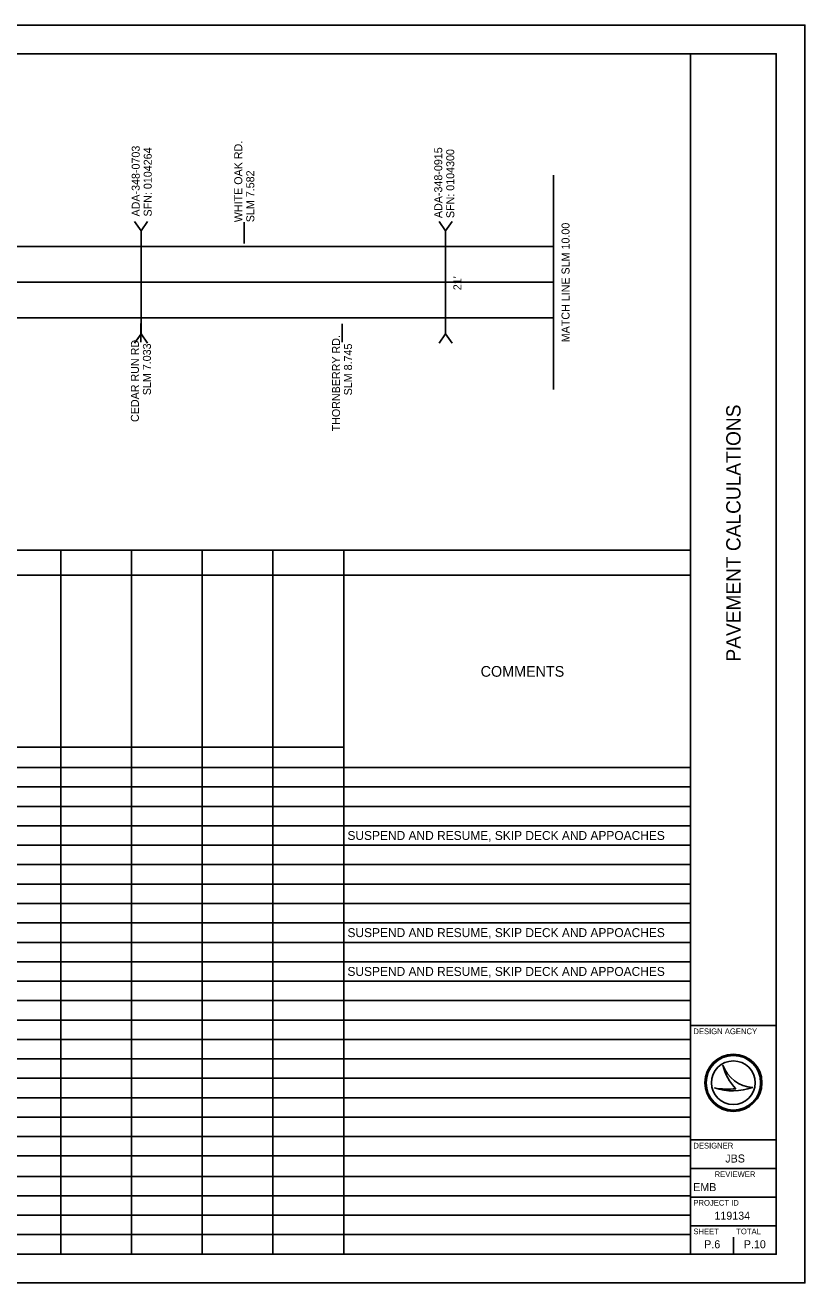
# Model space of a CAD drawing. Extents: x 0 to 34, y 0 to 22.
# Drawn here: x 20.36 to 34, y 0 to 22 of the extents above; entities that cross this region are included whole.
import ezdxf

# ---------------------------------------------------------------- set-up
doc = ezdxf.new("R2010")
doc.units = 0
for name, color, linetype in [('Default', 7, 'Continuous'), ('SC_Scratch1', 7, 'Continuous'), ('SH_Border', 7, 'Continuous'), ('SH_Cut_Line', 7, 'Continuous'), ('SH_Data', 7, 'Continuous'), ('SH_Text', 7, 'Continuous')]:
    doc.layers.add(name, color=color, linetype=linetype)

msp = doc.modelspace()

# ---------------------------------------------------------------- linework, layer by layer
at = {"layer": 'Default'}
for p, q in [((1.5, 21.5), (32, 21.5)), ((32, 21.5), (32, 7.315)), ((3.206, 17.503), (29.606, 17.503)), ((16.03, 12.819), (32, 12.819)), ((20.987, 12.819), (20.987, 0.503)), ((22.224, 12.819), (22.224, 0.503)), ((23.46, 12.819), (23.46, 0.503)), ((24.696, 12.819), (24.696, 0.503)), ((25.933, 12.819), (25.933, 0.503)), ((16.052, 12.378), (32, 12.378)), ((16.052, 9.371), (25.933, 9.371)), ((16.052, 9.014), (32, 9.014)), ((16.052, 8.674), (32, 8.674)), ((16.052, 8.335), (32, 8.335)), ((16.052, 7.995), (32, 7.995)), ((16.052, 7.655), (32, 7.655)), ((16.052, 7.315), (32, 7.315)), ((16.052, 6.976), (32, 6.976)), ((32, 6.976), (32, 5.277)), ((16.052, 6.636), (32, 6.636)), ((16.052, 6.296), (32, 6.296)), ((16.052, 5.956), (32, 5.956)), ((16.052, 5.617), (32, 5.617)), ((16.052, 5.277), (32, 5.277)), ((16.052, 4.937), (32, 4.937)), ((32, 4.937), (32, 0.503)), ((16.052, 4.597), (32, 4.597)), ((16.052, 4.258), (32, 4.258)), ((16.052, 3.918), (32, 3.918)), ((16.052, 3.578), (32, 3.578)), ((16.052, 3.238), (32, 3.238)), ((16.052, 2.899), (32, 2.899)), ((16.052, 2.559), (32, 2.559)), ((16.052, 2.219), (32, 2.219)), ((16.052, 1.862), (32, 1.862)), ((16.052, 1.523), (32, 1.523)), ((16.052, 1.183), (32, 1.183)), ((16.052, 0.843), (32, 0.843)), ((16.03, 0.503), (32, 0.503))]:
    msp.add_line(p, q, dxfattribs=at)
msp.add_lwpolyline([(3.206, 18.128), (3.206, 16.878), (29.606, 16.878), (29.606, 18.128), (29.606, 18.128), (3.206, 18.128), (3.206, 16.878), (29.606, 16.878), (29.606, 18.128)], close=True, dxfattribs=at)
at = {"layer": 'SC_Scratch1'}
for points in [[(10.754, 18.128), (29.606, 18.128), (29.606, 16.878), (10.754, 16.878)], [(19.825, 18.128), (29.606, 18.128), (29.606, 16.878), (19.825, 16.878)]]:
    msp.add_lwpolyline(points, close=True, dxfattribs=at)
at = {"layer": 'SH_Border'}
for p, q in [((32, 0.5), (32, 21.5)), ((32, 4.5), (33.5, 4.5)), ((32, 2.5), (33.5, 2.5)), ((32, 2), (33.5, 2)), ((32, 1.5), (33.5, 1.5)), ((32, 1), (33.5, 1))]:
    msp.add_line(p, q, dxfattribs=at)
msp.add_lwpolyline([(1.5, 21.5), (33.5, 21.5), (33.5, 0.5), (1.5, 0.5)], close=True, dxfattribs=at)
at = {"layer": 'SH_Cut_Line'}
msp.add_lwpolyline([(0, 0), (34, 0), (34, 22), (0, 22)], close=True, dxfattribs=at)
at = {"layer": 'SH_Data'}
for p, q in [((32.567, 3.81), (32.567, 3.81)), ((32.417, 3.41), (32.417, 3.41)), ((32.75, 3.5), (32.75, 3.5)), ((33.087, 3.419), (33.087, 3.419)), ((32.375, 0.675), (32.375, 0.675)), ((32.75, 0.5), (32.75, 0.8))]:
    msp.add_line(p, q, dxfattribs=at)
msp.add_lwpolyline([(19.825, 18.128), (29.606, 18.128), (29.606, 16.878), (19.825, 16.878)], close=True, dxfattribs=at)
for radius in [0.5, 0.477, 0.477, 0.382]:
    msp.add_circle((32.75, 3.5), radius, dxfattribs=at)
for centre, radius, start, end in [((33.116, 3.998), 0.58, 198.9257, 198.9319), ((33.347, 3.97), 0.796, 191.6379, 191.6421), ((33.116, 3.998), 0.58, 198.9319, 267.1657), ((33.347, 3.97), 0.796, 191.6421, 226.0947), ((32.739, 4.37), 1.013, 251.4576, 290.0832), ((32.648, 4.654), 1.266, 259.4964, 259.4995), ((32.739, 4.37), 1.013, 251.4527, 251.4576), ((32.648, 4.654), 1.266, 259.4995, 276.6672)]:
    msp.add_arc(centre, radius, start, end, dxfattribs=at)
at = {"layer": 'SH_Text'}
for p, q in [((29.606, 19.378), (29.606, 15.628)), ((22.388, 18.403), (22.273, 18.567)), ((22.388, 18.403), (22.503, 18.567)), ((24.194, 18.178), (24.194, 18.553)), ((27.716, 18.403), (27.602, 18.567)), ((27.716, 18.403), (27.831, 18.567)), ((22.388, 16.603), (22.388, 18.403)), ((27.716, 16.603), (27.716, 18.403)), ((22.393, 18.128), (22.268, 18.128)), ((22.393, 18.128), (22.518, 18.128)), ((3.206, 16.878), (29.606, 16.878)), ((22.386, 16.782), (22.386, 16.453)), ((25.904, 16.775), (25.904, 16.453)), ((22.388, 16.603), (22.273, 16.439)), ((22.388, 16.603), (22.503, 16.439)), ((27.716, 16.603), (27.602, 16.439)), ((27.716, 16.603), (27.831, 16.439))]:
    msp.add_line(p, q, dxfattribs=at)

# ---------------------------------------------------------------- texts
at = {"layer": 'Default'}
for s, height, p in [('COMMENTS', 0.1875, (28.329, 10.602)), ('SUSPEND AND RESUME, SKIP DECK AND APPOACHES', 0.15629, (25.999, 7.747)), ('SUSPEND AND RESUME, SKIP DECK AND APPOACHES', 0.15629, (25.999, 6.048)), ('SUSPEND AND RESUME, SKIP DECK AND APPOACHES', 0.15629, (25.999, 5.369))]:
    msp.add_text(s, height=height, dxfattribs=at).set_placement(p)
at = {"layer": 'SH_Data'}
msp.add_text('PAVEMENT CALCULATIONS', height=0.25, rotation=90, dxfattribs=at).set_placement((32.875, 10.868))
for s, height, p in [('DESIGN AGENCY', 0.1, (32.05, 4.35)), ('DESIGNER', 0.1, (32.05, 2.35)), ('JBS', 0.14, (32.608, 2.105)), ('REVIEWER', 0.1, (32.422, 1.85)), ('EMB', 0.14, (32.047, 1.605)), ('PROJECT ID', 0.1, (32.05, 1.35)), ('119134', 0.14, (32.418, 1.105)), ('SHEET', 0.1, (32.05, 0.85)), ('TOTAL', 0.1, (32.8, 0.85)), ('P.6', 0.14, (32.239, 0.605)), ('P.10', 0.14, (32.932, 0.605))]:
    msp.add_text(s, height=height, dxfattribs=at).set_placement(p)
at = {"layer": 'SH_Text'}
for s, p in [('ADA-348-0703', (22.365, 18.653)), ('SFN: 0104264', (22.575, 18.653)), ('WHITE OAK RD.', (24.159, 18.553)), ('ADA-348-0915', (27.657, 18.625)), ('SFN: 0104300', (27.867, 18.625)), ('SLM 7.582', (24.369, 18.553)), ('MATCH LINE SLM 10.00', (29.884, 16.453)), ('+', (27.782, 17.45)), ("21'", (27.992, 17.364)), ('CEDAR RUN RD.', (22.351, 15.059)), ('THORNBERRY RD.', (25.869, 14.894)), ('SLM 7.033', (22.561, 15.527)), ('SLM 8.745', (26.079, 15.524))]:
    msp.add_text(s, height=0.14, rotation=90, dxfattribs=at).set_placement(p)

doc.saveas('drawing.dxf')
